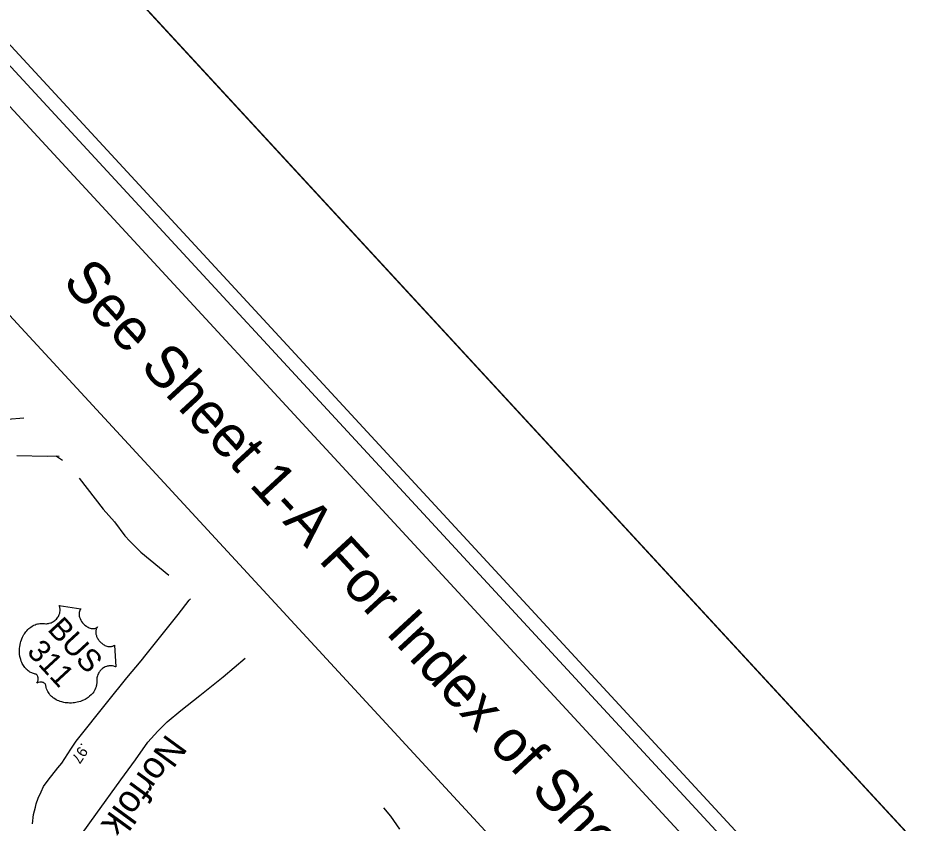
# Model space of a CAD drawing. Extents: x 1695041 to 1706254, y 786537 to 798223.
# Drawn here: x 1703356.2 to 1703837.1, y 797134.4 to 797569.4 of the extents above; entities that cross this region are included whole.
import ezdxf

# ---------------------------------------------------------------- set-up
doc = ezdxf.new("R2010")
doc.units = 0
for name, color, linetype in [('Default', 7, 'Continuous'), ('Old_Level_13', 7, 'Continuous'), ('Old_Level_29', 7, 'Continuous'), ('Old_Level_32', 7, 'Continuous'), ('Sheet Cutting Line CELL', 7, 'Continuous'), ('Sheet Plot Border Inside CELL', 7, 'Continuous'), ('Sheet Plot Border Outside CELL', 7, 'Continuous'), ('Sheet Title CELL', 7, 'Continuous')]:
    doc.layers.add(name, color=color, linetype=linetype)

msp = doc.modelspace()

# ---------------------------------------------------------------- linework, layer by layer
at = {"layer": 'Default'}
msp.add_line((1703835.77, 796884.26), (1703207.65, 797564.73), dxfattribs=at)
for points in [[(1703377.11, 797332.55), (1703380.38, 797330.52)], [(1703378.57, 797332.48), (1703377.11, 797332.55)], [(1703389.35, 797320.81), (1703402.4, 797304), (1703408.38, 797297.07), (1703414.06, 797289.65), (1703416.67, 797286.66), (1703422.6, 797280.71), (1703437.78, 797268.34)]]:
    msp.add_lwpolyline(points, dxfattribs=at)
msp.add_lwpolyline([(1703390.34, 797250.11), (1703390.07, 797249.83), (1703389.8, 797249.45), (1703389.67, 797249.24), (1703389.49, 797248.78), (1703389.33, 797248.16), (1703389.28, 797247.45), (1703389.33, 797246.73), (1703389.4, 797246.29), (1703389.58, 797245.6), (1703389.85, 797244.86), (1703390.22, 797244.12), (1703390.65, 797243.41), (1703391.19, 797242.68), (1703391.77, 797242.02), (1703392.47, 797241.37), (1703393.34, 797240.74), (1703393.76, 797240.46), (1703394.26, 797240.19), (1703394.76, 797239.96), (1703395.35, 797239.76), (1703395.86, 797239.62), (1703396.29, 797239.54), (1703396.97, 797239.5), (1703397.59, 797239.54), (1703397.9, 797239.6), (1703398.19, 797239.68), (1703398.74, 797239.91), (1703398.96, 797240.04), (1703399.36, 797240.36), (1703399.07, 797240.04), (1703398.9, 797239.83), (1703398.75, 797239.6), (1703398.62, 797239.33), (1703398.47, 797238.92), (1703398.37, 797238.53), (1703398.29, 797237.9), (1703398.29, 797237.54), (1703398.31, 797237.24), (1703398.42, 797236.48), (1703398.65, 797235.69), (1703398.77, 797235.31), (1703398.93, 797234.95), (1703399.15, 797234.51), (1703399.39, 797234.07), (1703399.66, 797233.66), (1703399.94, 797233.25), (1703400.25, 797232.85), (1703400.53, 797232.54), (1703400.87, 797232.18), (1703401.21, 797231.85), (1703401.57, 797231.54), (1703401.99, 797231.21), (1703402.35, 797230.97), (1703402.84, 797230.65), (1703403.31, 797230.41), (1703403.75, 797230.21), (1703404.37, 797229.99), (1703404.9, 797229.85), (1703405.33, 797229.78), (1703405.88, 797229.74), (1703406.46, 797229.76), (1703406.85, 797229.81), (1703407.21, 797229.92), (1703407.57, 797230.05), (1703407.9, 797230.24), (1703408.17, 797230.43), (1703408.38, 797230.61), (1703409.24, 797218.77), (1703409.03, 797218.87), (1703408.51, 797219.08), (1703408.06, 797219.21), (1703407.3, 797219.37), (1703406.93, 797219.41), (1703406.56, 797219.43), (1703406.18, 797219.43), (1703405.84, 797219.42), (1703405.39, 797219.37), (1703404.95, 797219.29), (1703404.49, 797219.19), (1703404.11, 797219.07), (1703403.37, 797218.77), (1703402.93, 797218.55), (1703402.57, 797218.35), (1703401.89, 797217.87), (1703401.58, 797217.62), (1703401.3, 797217.35), (1703401.01, 797217.06), (1703400.74, 797216.76), (1703400.49, 797216.43), (1703400.27, 797216.14), (1703400.02, 797215.75), (1703399.75, 797215.28), (1703399.52, 797214.79), (1703399.22, 797213.93), (1703398.98, 797212.98), (1703398.91, 797212.38), (1703398.88, 797211.83), (1703398.91, 797211.08), (1703398.92, 797210.67), (1703398.9, 797210.16), (1703398.8, 797209.28), (1703398.73, 797208.89), (1703398.63, 797208.47), (1703398.51, 797208.06), (1703398.36, 797207.63), (1703398.23, 797207.27), (1703397.87, 797206.49), (1703397.46, 797205.79), (1703397.23, 797205.43), (1703396.68, 797204.69), (1703396.4, 797204.34), (1703395.79, 797203.68), (1703395, 797202.95), (1703394.2, 797202.32), (1703393.19, 797201.65), (1703392.56, 797201.28), (1703391.79, 797200.9), (1703391.1, 797200.59), (1703390.03, 797200.18), (1703389.22, 797199.94), (1703388.22, 797199.69), (1703387.6, 797199.56), (1703386.91, 797199.45), (1703386.08, 797199.36), (1703385.17, 797199.29), (1703384.16, 797199.29), (1703383.37, 797199.32), (1703382.41, 797199.41), (1703381.84, 797199.49), (1703381.07, 797199.63), (1703380.07, 797199.87), (1703379.14, 797200.16), (1703378.38, 797200.44), (1703377.75, 797200.72), (1703376.96, 797201.11), (1703375.76, 797201.86), (1703375.34, 797202.16), (1703374.88, 797202.53), (1703374.46, 797202.9), (1703374.07, 797203.27), (1703373.58, 797203.81), (1703373.13, 797204.37), (1703372.74, 797204.94), (1703372.37, 797205.56), (1703372.03, 797206.25), (1703371.77, 797206.92), (1703371.56, 797207.65), (1703371.31, 797208.98), (1703371.21, 797209.35), (1703371.12, 797209.52), (1703370.84, 797209.86), (1703370.49, 797210.11), (1703370.08, 797210.3), (1703369.8, 797210.4), (1703369.4, 797210.5), (1703369.07, 797210.55), (1703368.63, 797210.58), (1703368.3, 797210.57), (1703368.04, 797210.56), (1703367.45, 797210.45), (1703367.19, 797210.37), (1703366.88, 797210.25), (1703366.47, 797210.01), (1703366.8, 797210.52), (1703366.96, 797210.9), (1703367.07, 797211.27), (1703367.15, 797211.62), (1703367.2, 797212.11), (1703367.21, 797212.51), (1703367.18, 797212.96), (1703367.09, 797213.39), (1703367, 797213.71), (1703366.89, 797213.99), (1703366.73, 797214.29), (1703366.56, 797214.5), (1703366.4, 797214.66), (1703366.14, 797214.84), (1703365.63, 797214.95), (1703365.16, 797215.05), (1703364.67, 797215.19), (1703364.12, 797215.38), (1703363.73, 797215.54), (1703363.3, 797215.75), (1703362.81, 797216.02), (1703362.32, 797216.34), (1703361.84, 797216.69), (1703361.43, 797217.01), (1703361.01, 797217.39), (1703360.66, 797217.74), (1703360.31, 797218.13), (1703360.01, 797218.51), (1703359.66, 797218.96), (1703359.26, 797219.55), (1703358.97, 797220.07), (1703358.67, 797220.63), (1703358.39, 797221.23), (1703358.12, 797221.9), (1703357.82, 797222.77), (1703357.64, 797223.4), (1703357.41, 797224.44), (1703357.22, 797225.75), (1703357.15, 797226.8), (1703357.14, 797227.61), (1703357.21, 797228.87), (1703357.29, 797229.65), (1703357.51, 797230.96), (1703357.72, 797231.86), (1703357.9, 797232.49), (1703358.22, 797233.46), (1703358.46, 797234.04), (1703358.82, 797234.86), (1703359.19, 797235.57), (1703359.55, 797236.23), (1703359.81, 797236.63), (1703360.27, 797237.29), (1703360.61, 797237.76), (1703361.11, 797238.36), (1703361.67, 797238.95), (1703362.22, 797239.47), (1703362.69, 797239.88), (1703363.27, 797240.32), (1703363.93, 797240.76), (1703364.51, 797241.1), (1703364.96, 797241.32), (1703365.52, 797241.57), (1703366.17, 797241.82), (1703366.83, 797242.01), (1703367.4, 797242.14), (1703368.05, 797242.24), (1703368.64, 797242.29), (1703369.34, 797242.29), (1703370.02, 797242.25), (1703370.6, 797242.17), (1703371.35, 797242.13), (1703371.77, 797242.14), (1703372.33, 797242.19), (1703372.81, 797242.27), (1703373.23, 797242.37), (1703373.82, 797242.53), (1703374.23, 797242.68), (1703374.84, 797242.95), (1703375.23, 797243.16), (1703375.72, 797243.47), (1703376.16, 797243.78), (1703376.67, 797244.21), (1703377.06, 797244.59), (1703377.48, 797245.08), (1703377.85, 797245.58), (1703378.15, 797246.05), (1703378.44, 797246.64), (1703378.63, 797247.1), (1703378.84, 797247.78), (1703378.98, 797248.45), (1703379.04, 797249.06), (1703379.07, 797249.64), (1703379.03, 797250.14), (1703378.97, 797250.6), (1703378.86, 797251.14), (1703378.72, 797251.63), (1703378.61, 797251.91)], close=True, dxfattribs=at)
at = {"layer": 'Old_Level_13'}
for points in [[(1702974.97, 797316.73), (1702982.4, 797317.52), (1703001.26, 797319.73), (1703020.51, 797321.65), (1703035.57, 797323.26), (1703058.15, 797324.99), (1703080.74, 797326.95), (1703098, 797328.45), (1703112.41, 797330.08), (1703122.72, 797331.11), (1703135.99, 797332.6), (1703160.19, 797335.29), (1703178.25, 797336.88), (1703197.69, 797338.61), (1703216.47, 797340.11), (1703234.88, 797342.01), (1703246.09, 797342.73), (1703266.58, 797344.56), (1703287.34, 797346.48), (1703309.13, 797348.5), (1703329.25, 797350.46), (1703350.62, 797352.68), (1703359.41, 797353.24)], [(1703321.31, 797061.94), (1703332.38, 797068.88), (1703344.54, 797076.96), (1703351.89, 797080.84), (1703356.03, 797084.25), (1703359.25, 797087.45), (1703363.77, 797092.08), (1703367.17, 797096.04), (1703371.9, 797102.36), (1703383.58, 797118.52), (1703398.38, 797139.03), (1703411.79, 797157.78), (1703419.75, 797168.69), (1703426.47, 797178.18), (1703431.77, 797184.16), (1703436.92, 797189.22), (1703444.25, 797195.29), (1703454.5, 797203.41), (1703467.2, 797213.48), (1703479.07, 797223.61)]]:
    msp.add_lwpolyline(points, dxfattribs=at)
at = {"layer": 'Old_Level_29'}
msp.add_lwpolyline([(1703364.15, 797134.1), (1703364.73, 797139.07), (1703365.71, 797143.11), (1703366.18, 797144.92), (1703367.27, 797147.99), (1703368.83, 797151.4), (1703370.16, 797154.2), (1703372.61, 797157.64), (1703377.87, 797164.22), (1703380.04, 797166.89), (1703384.9, 797174.39), (1703387.68, 797178.66), (1703404.82, 797200.04), (1703415.2, 797212.92), (1703422.79, 797222.11), (1703425.61, 797225.52), (1703435.65, 797238.19), (1703442.76, 797247.07), (1703448.81, 797254.79), (1703449.5, 797255.64)], dxfattribs=at)
at = {"layer": 'Old_Level_32'}
for points in [[(1703377.11, 797332.55), (1703372.17, 797332.53), (1703355.65, 797332.84)], [(1703553.78, 797142.67), (1703557.42, 797138.26), (1703562.3, 797131.12)]]:
    msp.add_lwpolyline(points, dxfattribs=at)
at = {"layer": 'Sheet Cutting Line CELL'}
msp.add_line((1702826.93, 798222.79), (1706253.58, 794510.54), dxfattribs=at)
at = {"layer": 'Sheet Plot Border Inside CELL'}
msp.add_lwpolyline([(1700478.01, 796001.5), (1703869.05, 792327.83), (1706194.94, 794474.78), (1702803.9, 798148.45)], close=True, dxfattribs=at)
at = {"layer": 'Sheet Plot Border Outside CELL'}
msp.add_lwpolyline([(1706253.58, 794510.54), (1702826.93, 798222.79), (1700402.1, 795984.5), (1703828.75, 792272.26)], close=True, dxfattribs=at)
at = {"layer": 'Sheet Title CELL'}
for points in [[(1706143.56, 794519.16), (1703131.99, 797781.79)], [(1706122.34, 794520.04), (1703232.91, 797650.29)]]:
    msp.add_lwpolyline(points, dxfattribs=at)

# ---------------------------------------------------------------- texts
at = {"layer": 'Default'}
for s, height, rotation, p in [('BUS', 12.01, 312.7091, (1703371.77, 797238.8)), ('311', 12.01, 312.7091, (1703360.66, 797226.63)), ('Norfolk', 14.412, 233.877, (1703436.71, 797183.16)), ('.97', 5.775, 237.0513, (1703390.78, 797178.16))]:
    msp.add_text(s, height=height, rotation=rotation, dxfattribs=at).set_placement(p)
at = {"layer": 'Sheet Title CELL'}
msp.add_text('See Sheet 1-A For Index of Sheets', height=22.5, rotation=312.7091, dxfattribs=at).set_placement((1703379.74, 797426.2))

doc.saveas('drawing.dxf')
